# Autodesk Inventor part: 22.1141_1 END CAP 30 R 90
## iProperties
Created: 2012-08
Part Number: 22.1141_1 END CAP 30 R 90
Document SubType Name: Modeling
Designer: Administrator
Density: 1 g/cm^3
Mass: 1.86363 g
Surface Area: 22.3591 cm^2
Volume: 1.86363 cm^3
Author: Administrator
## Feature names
1. Base1
